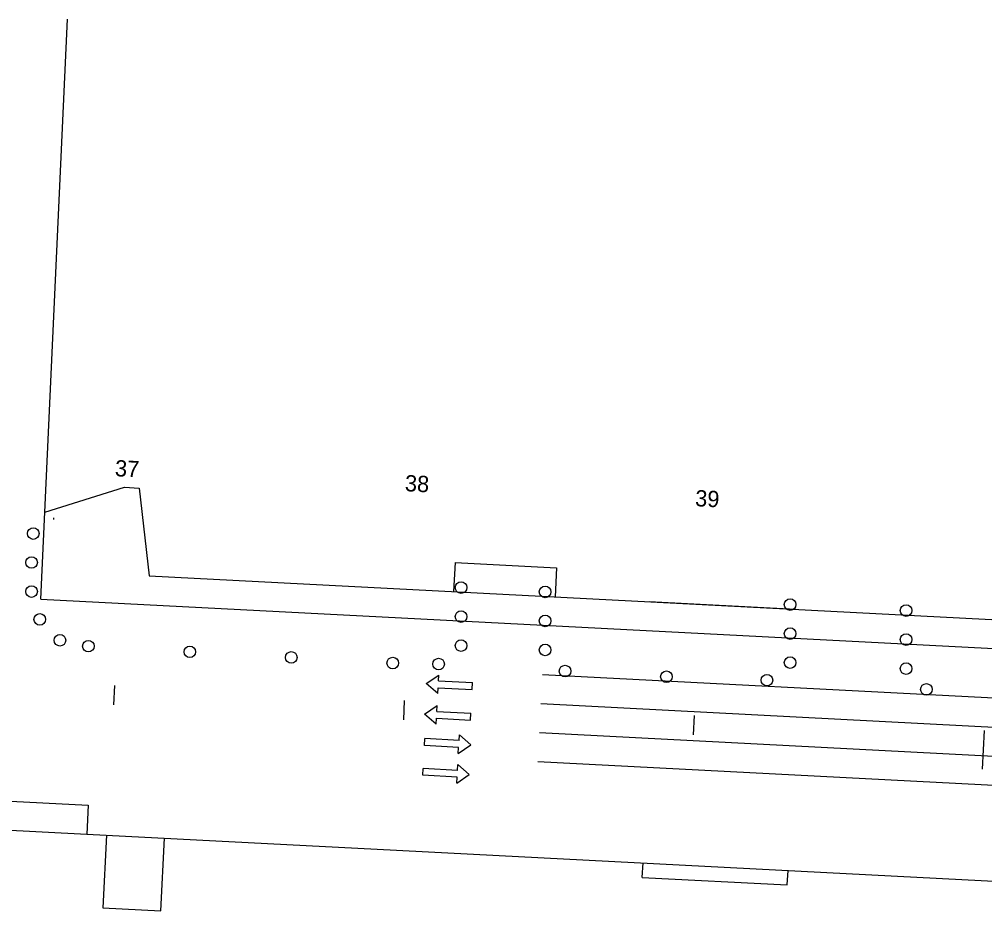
# Model space of a CAD drawing. Extents: x 0 to 1361828, y 0 to 1470398.
# Drawn here: x 682944.5 to 683277, y 734964.8 to 735271.9 of the extents above; entities that cross this region are included whole.
import ezdxf

# ---------------------------------------------------------------- set-up
doc = ezdxf.new("R2010")
doc.units = 0
for name, color, linetype in [('$', 7, 'Continuous'), ('MOT Stage 1', 7, 'Continuous'), ('MOT Stage 1 Lanes', 7, 'Continuous'), ('R_Horz Alg Station', 7, 'Continuous'), ('R_TYPE_A_CURB', 7, 'Continuous'), ('RW-EX', 7, 'Continuous'), ('RW-PR', 7, 'Continuous')]:
    doc.layers.add(name, color=color, linetype=linetype)

# ---------------------------------------------------------------- blocks, each defined once
blk = doc.blocks.new('BAREL_1596')
at = {"layer": 'MOT Stage 1'}
blk.add_circle((0, 0.01), 2.88, dxfattribs=at)
blk = doc.blocks.new('BAREL_1597')
at = {"layer": 'MOT Stage 1'}
blk.add_circle((0, 0.01), 2.88, dxfattribs=at)
blk = doc.blocks.new('BAREL_1598')
at = {"layer": 'MOT Stage 1'}
blk.add_circle((0, 0.01), 2.88, dxfattribs=at)
blk = doc.blocks.new('BAREL_1599')
at = {"layer": 'MOT Stage 1'}
blk.add_circle((0, 0.01), 2.88, dxfattribs=at)
blk = doc.blocks.new('BAREL_1600')
at = {"layer": 'MOT Stage 1'}
blk.add_circle((0, 0.01), 2.88, dxfattribs=at)
blk = doc.blocks.new('BAREL_1601')
at = {"layer": 'MOT Stage 1'}
blk.add_circle((0, 0.01), 2.88, dxfattribs=at)
blk = doc.blocks.new('BAREL_1602')
at = {"layer": 'MOT Stage 1'}
blk.add_circle((0, 0.01), 2.88, dxfattribs=at)
blk = doc.blocks.new('BAREL_1603')
at = {"layer": 'MOT Stage 1'}
blk.add_circle((0, 0.01), 2.88, dxfattribs=at)
blk = doc.blocks.new('BAREL_1604')
at = {"layer": 'MOT Stage 1'}
blk.add_circle((0, 0.01), 2.88, dxfattribs=at)
blk = doc.blocks.new('BAREL_1605')
at = {"layer": 'MOT Stage 1'}
blk.add_circle((0, 0.01), 2.88, dxfattribs=at)
blk = doc.blocks.new('BAREL_1606')
at = {"layer": 'MOT Stage 1'}
blk.add_circle((0, 0.01), 2.88, dxfattribs=at)
blk = doc.blocks.new('BAREL_1607')
at = {"layer": 'MOT Stage 1'}
blk.add_circle((0, 0.01), 2.88, dxfattribs=at)
blk = doc.blocks.new('BAREL_1608')
at = {"layer": 'MOT Stage 1'}
blk.add_circle((0, 0.01), 2.88, dxfattribs=at)
blk = doc.blocks.new('BAREL_1609')
at = {"layer": 'MOT Stage 1'}
blk.add_circle((0, 0.01), 2.88, dxfattribs=at)
blk = doc.blocks.new('BAREL_1636')
at = {"layer": 'MOT Stage 1'}
blk.add_circle((0, 0.01), 2.88, dxfattribs=at)
blk = doc.blocks.new('BAREL_1637')
at = {"layer": 'MOT Stage 1'}
blk.add_circle((0, 0.01), 2.88, dxfattribs=at)
blk = doc.blocks.new('BAREL_1638')
at = {"layer": 'MOT Stage 1'}
blk.add_circle((0, 0.01), 2.88, dxfattribs=at)
blk = doc.blocks.new('BAREL_1639')
at = {"layer": 'MOT Stage 1'}
blk.add_circle((0, 0.01), 2.88, dxfattribs=at)
blk = doc.blocks.new('BAREL_1640')
at = {"layer": 'MOT Stage 1'}
blk.add_circle((0, 0.01), 2.88, dxfattribs=at)
blk = doc.blocks.new('SARROW_191')
at = {"layer": 'MOT Stage 1'}
for p, q in [((-6, -29.42), (-6, 0)), ((0, 0), (-6, 0)), ((0, -29.42), (0, 0)), ((-6, -29.42), (-11, -29.42)), ((-3, -39.81), (-11, -29.42)), ((5, -29.42), (-3, -39.81)), ((5, -29.42), (0, -29.42))]:
    blk.add_line(p, q, dxfattribs=at)
blk = doc.blocks.new('SARROW_192')
at = {"layer": 'MOT Stage 1'}
for p, q in [((-6, -29.42), (-6, 0)), ((0, 0), (-6, 0)), ((0, -29.42), (0, 0)), ((-6, -29.42), (-11, -29.42)), ((-3, -39.81), (-11, -29.42)), ((5, -29.42), (-3, -39.81)), ((5, -29.42), (0, -29.42))]:
    blk.add_line(p, q, dxfattribs=at)
blk = doc.blocks.new('SARROW_193')
at = {"layer": 'MOT Stage 1'}
for p, q in [((-6, -29.42), (-6, 0)), ((0, 0), (-6, 0)), ((0, -29.42), (0, 0)), ((-6, -29.42), (-11, -29.42)), ((-3, -39.81), (-11, -29.42)), ((5, -29.42), (-3, -39.81)), ((5, -29.42), (0, -29.42))]:
    blk.add_line(p, q, dxfattribs=at)
blk = doc.blocks.new('SARROW_194')
at = {"layer": 'MOT Stage 1'}
for p, q in [((0, 0), (-6, 0)), ((0, -29.42), (0, 0)), ((-6, -29.42), (-6, 0)), ((-6, -29.42), (-11, -29.42)), ((-3, -39.81), (-11, -29.42)), ((5, -29.42), (-3, -39.81)), ((5, -29.42), (0, -29.42))]:
    blk.add_line(p, q, dxfattribs=at)
blk = doc.blocks.new('BAREL_1665')
at = {"layer": 'MOT Stage 1'}
blk.add_circle((0, 0.01), 2.88, dxfattribs=at)
blk = doc.blocks.new('BAREL_1666')
at = {"layer": 'MOT Stage 1'}
blk.add_circle((0, 0.01), 2.88, dxfattribs=at)
blk = doc.blocks.new('BAREL_1667')
at = {"layer": 'MOT Stage 1'}
blk.add_circle((0, 0.01), 2.88, dxfattribs=at)
blk = doc.blocks.new('BAREL_1668')
at = {"layer": 'MOT Stage 1'}
blk.add_circle((0, 0.01), 2.88, dxfattribs=at)
blk = doc.blocks.new('BAREL_1669')
at = {"layer": 'MOT Stage 1'}
blk.add_circle((0, 0.01), 2.88, dxfattribs=at)
blk = doc.blocks.new('BAREL_1670')
at = {"layer": 'MOT Stage 1'}
blk.add_circle((0, 0.01), 2.88, dxfattribs=at)
blk = doc.blocks.new('BAREL_1671')
at = {"layer": 'MOT Stage 1'}
blk.add_circle((0, 0.01), 2.88, dxfattribs=at)

msp = doc.modelspace()

# ---------------------------------------------------------------- linework, layer by layer
at = {"layer": 'MOT Stage 1 Lanes'}
for p, q in [((683124.65, 735046.17), (683304.73, 735036.86)), ((683124.13, 735036.18), (683304.21, 735026.87)), ((683123.62, 735026.19), (683303.69, 735016.89)), ((683123.1, 735016.21), (683303.18, 735006.9))]:
    msp.add_line(p, q, dxfattribs=at)
at = {"layer": 'R_Horz Alg Station'}
for points in [[(682977.23, 735042.44), (682976.88, 735035.78)], [(683077.09, 735037.28), (683076.75, 735030.62)], [(683176.96, 735032.11), (683176.62, 735025.46)], [(683276.83, 735026.95), (683276.14, 735013.64)]]:
    msp.add_lwpolyline(points, dxfattribs=at)
at = {"layer": 'R_TYPE_A_CURB'}
for p, q in [((682956.36, 735099.63), (682956.39, 735100.2)), ((683161.46, 735071.3), (683211.89, 735068.69))]:
    msp.add_line(p, q, dxfattribs=at)
at = {"layer": 'RW-EX'}
for p, q in [((682951.92, 735072.12), (682961.1, 735271.9)), ((682951.92, 735072.12), (683440.41, 735046.87)), ((682628.3, 735018.75), (682968.24, 735001.18))]:
    msp.add_line(p, q, dxfattribs=at)
msp.add_lwpolyline([(682968.24, 735001.18), (682967.74, 734991.19), (683067.68, 734986.03), (683317.82, 734973.1), (683318.3, 734983.09), (683436.82, 734976.96)], dxfattribs=at)
at = {"layer": 'RW-PR'}
for p, q in [((683094.57, 735084.77), (683094.05, 735074.78)), ((683094.57, 735084.77), (683129.52, 735082.96)), ((683129.52, 735082.96), (683129.01, 735072.98)), ((682627.74, 735008.76), (682967.74, 734991.19)), ((683159.06, 734976.3), (683159.31, 734981.29)), ((683208.99, 734973.72), (683209.25, 734978.71)), ((683159.06, 734976.3), (683208.99, 734973.72))]:
    msp.add_line(p, q, dxfattribs=at)
for points in [[(682953.3, 735102.08), (682980.75, 735110.68), (682985.75, 735110.42), (682989.19, 735080.2), (683277.18, 735065.32), (683449.96, 735056.39), (683478.52, 735054.93), (683538.96, 735061.84)], [(682974.56, 734990.84), (682973.27, 734965.87), (682993.24, 734964.84), (682994.53, 734989.81)]]:
    msp.add_lwpolyline(points, dxfattribs=at)

# ---------------------------------------------------------------- block references
at = {"layer": 'MOT Stage 1'}
for name, p, xscale, yscale, rotation in [('BAREL_1636', (682949.3, 735094.76), 0.6945420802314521, 0.6945420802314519, 87.04179557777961), ('BAREL_1637', (682948.71, 735084.78), 0.6945420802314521, 0.6945420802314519, 87.04179557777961), ('BAREL_1638', (682948.71, 735074.78), 0.6945420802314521, 0.6945420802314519, 87.04179557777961), ('BAREL_1596', (683096.63, 735076.15), 0.6945420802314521, 0.6945420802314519, 87.04179557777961), ('BAREL_1599', (683125.59, 735074.66), 0.6945420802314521, 0.6945420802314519, 87.04179557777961), ('BAREL_1603', (683209.98, 735070.29), 0.6945420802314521, 0.6945420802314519, 87.04179557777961), ('BAREL_1604', (683249.93, 735068.23), 0.6945420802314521, 0.6945420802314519, 87.04179557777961), ('BAREL_1639', (682951.54, 735065.19), 0.6945420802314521, 0.6945420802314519, 87.04179557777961), ('BAREL_1597', (683096.63, 735066.15), 0.6945420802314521, 0.6945420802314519, 87.04179557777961), ('BAREL_1600', (683125.59, 735064.66), 0.6945420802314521, 0.6945420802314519, 87.04179557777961), ('BAREL_1605', (683209.98, 735060.29), 0.6945420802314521, 0.6945420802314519, 87.04179557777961), ('BAREL_1640', (682958.48, 735057.99), 0.6945420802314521, 0.6945420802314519, 87.04179557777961), ('BAREL_1607', (683249.93, 735058.23), 0.6945420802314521, 0.6945420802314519, 87.04179557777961), ('BAREL_1665', (682968.27, 735055.96), 0.6945420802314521, 0.6945420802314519, 87.04179557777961), ('BAREL_1666', (683003.22, 735054.02), 0.6945420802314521, 0.6945420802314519, 87.04179557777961), ('BAREL_1598', (683096.63, 735056.15), 0.6945420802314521, 0.6945420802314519, 87.04179557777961), ('BAREL_1601', (683125.59, 735054.66), 0.6945420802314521, 0.6945420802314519, 87.04179557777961), ('BAREL_1667', (683038.17, 735052.09), 0.6945420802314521, 0.6945420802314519, 87.04179557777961), ('BAREL_1668', (683073.11, 735050.15), 0.6945420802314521, 0.6945420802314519, 87.04179557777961), ('BAREL_1669', (683088.91, 735049.8), 0.6945420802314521, 0.6945420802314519, 87.04179557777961), ('BAREL_1606', (683209.98, 735050.29), 0.6945420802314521, 0.6945420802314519, 87.04179557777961), ('BAREL_1602', (683132.45, 735047.38), 0.6945420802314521, 0.6945420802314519, 115.570266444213), ('BAREL_1608', (683249.93, 735048.23), 0.6945420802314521, 0.6945420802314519, 87.04179557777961), ('SARROW_191', (683100.48, 735041.03), 0.39999999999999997, 0.4, -92.95654264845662), ('BAREL_1670', (683167.39, 735045.44), 0.6945420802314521, 0.6945420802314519, 115.570266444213), ('BAREL_1671', (683202.01, 735044.26), 0.6945420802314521, 0.6945420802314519, 87.04179557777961), ('BAREL_1609', (683256.92, 735041.09), 0.6945420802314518, 0.6945420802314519, 116.71114235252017), ('SARROW_192', (683099.89, 735030.51), 0.39999999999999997, 0.4, -92.95654264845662), ('SARROW_193', (683084.06, 735021.73), 0.40000000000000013, -0.40000000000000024, -93.38580215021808), ('SARROW_194', (683083.49, 735011.48), 0.40000000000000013, -0.40000000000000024, -93.38580215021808)]:
    msp.add_blockref(name, p, dxfattribs=dict(at, xscale=xscale, yscale=yscale, rotation=rotation))

# ---------------------------------------------------------------- texts
at = {"layer": '$'}
for s, p in [('37', (682977.32, 735114.53)), ('38', (683077.19, 735109.37)), ('39', (683177.16, 735104.2))]:
    msp.add_text(s, height=5.6, rotation=357.0415, dxfattribs=at).set_placement(p)

doc.saveas('drawing.dxf')
